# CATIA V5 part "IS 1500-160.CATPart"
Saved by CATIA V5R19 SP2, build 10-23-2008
Part number: IS 1500-160
Bounding box of the stored display mesh (mm): x -37.351 to 37.351, y -37.351 to 37.351, z 0 to 430
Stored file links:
  C:\Users\Bora\Desktop\3D Katı model\IS serisi\IS 1500\IS 1500-160.CATPart
  C:\Program Files\Dassault Systemes\B19\intel_a\reffiles\standard\MetricThickPitch.txt
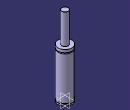
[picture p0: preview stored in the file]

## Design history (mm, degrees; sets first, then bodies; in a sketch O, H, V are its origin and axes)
Body1 (main body)
  Sketch1 on yz-plane, origin (0, 0, 0), H (0, 1, 0), V (0, 0, 1)
    point P1 (37.5, 251.5)
    point P4 (37.5, 246.5)
    point P7 (18, 429)
    point P9 (18, 429)
    point P13 (37.5, 251.5)
    point P14 (37.5, 246.5)
    line L1 (37.5, 251.5) -> (37.5, 267)
    line L2 (37.5, 13) -> (37.5, 246.5)
    line L3 (33.5, 13) -> (33.5, 8)
    arc A1 centre (17, 429) radius 1 from (18, 429) to (17, 430) ccw
    line L4 (18, 429) -> (18, 267)
    line L5 (37.5, 0) -> (37.5, 8)
    arc A2 centre (37.5, 249) radius 2.5 from (37.5, 251.5) to (37.5, 246.5) ccw
    line L6 (17, 430) -> (0, 430)
    point P15 (0, 430)
    line L7 (18, 267) -> (37.5, 267)
    line L8 (0, 0) -> (37.5, 0)
    line L9 (33.5, 8) -> (37.5, 8)
    line L10 (33.5, 13) -> (37.5, 13)
    coincidence: P15 V, P1 P13, P4 P14, P7 P9
    tangency: L6 A1
    horizontal: L7 H, L8 H, L9 H, L10 H
  Shaft1: profile Sketch1, axis Sketch1.V, angle 360
  Sketch2 on face of Shaft1 from Sketch1.L8, origin (0, 0, 0), H (1, 0, 0), V (0, -1, 0)
    point P1 (20, 0)
    distance P1 V = 20
  Hole1: placed by Sketch2, at (20, 0, 0) direction (0, 0, 1), diameter 6.647, depth 13, threaded "M8", thread diameter 8, thread depth 13, pitch 1.25
  CircPattern1: of Hole1, instances 4, angular step 90, axis from xy-plane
